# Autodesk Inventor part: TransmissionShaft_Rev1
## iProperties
Created: 2008-11
Part Number: TransmissionShaft_Rev1
Document SubType Name: Modeling
Designer: ETUDIANT
Author: ETUDIANT
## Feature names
1. Base1
